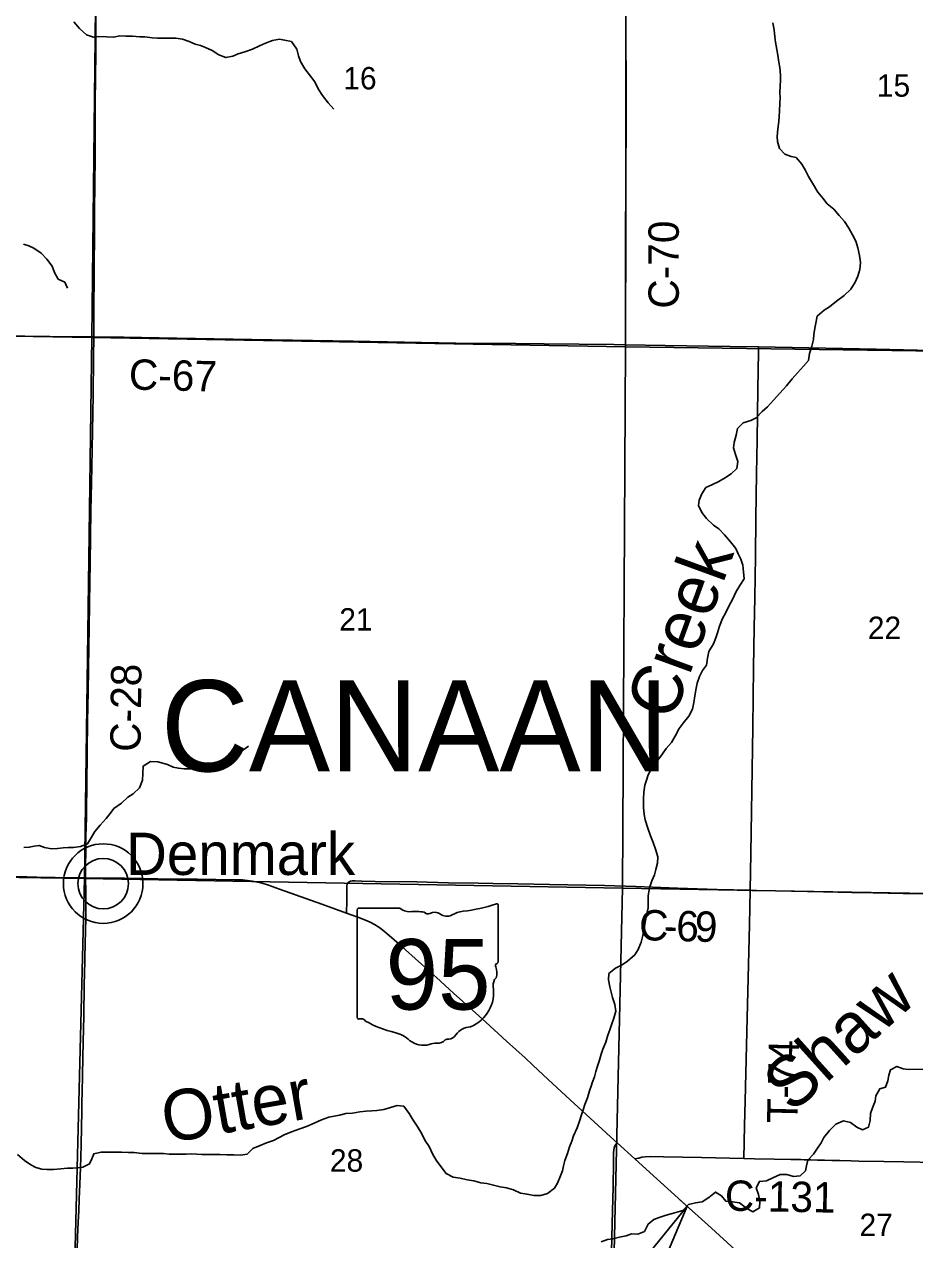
# Model space of a CAD drawing. Extents: x 0 to 34, y 0 to 22.
# Drawn here: x 4.92 to 6.585, y 17.017 to 19.29 of the extents above; entities that cross this region are included whole.
import ezdxf

# ---------------------------------------------------------------- set-up
doc = ezdxf.new("R2010")
doc.units = 0
for name, color, linetype in [('GM_X_City_Street', 7, 'Continuous'), ('GM_X_Corporation_Text', 7, 'Continuous'), ('GM_X_County_Road', 7, 'Continuous'), ('GM_X_County_Road_Text', 7, 'Continuous'), ('GM_X_Interchange_Ramps', 7, 'Continuous'), ('GM_X_Major_River_Text', 7, 'Continuous'), ('GM_X_Minor_Lake', 7, 'Continuous'), ('GM_X_Minor_River', 7, 'Continuous'), ('GM_X_Minor_River_Text', 7, 'Continuous'), ('GM_X_Section', 7, 'Continuous'), ('GM_X_State_Location', 7, 'Continuous'), ('GM_X_Township_Road_Text', 7, 'Continuous'), ('GM_X_Township_Text', 7, 'Continuous'), ('GM_X_Unincorporated_Location', 7, 'Continuous'), ('GM_X_Unincorporated_Text', 7, 'Continuous'), ('SH_Border', 7, 'Continuous'), ('SH_Cut_Line', 7, 'Continuous')]:
    doc.layers.add(name, color=color, linetype=linetype)

msp = doc.modelspace()

# ---------------------------------------------------------------- linework, layer by layer
at = {"layer": 'GM_X_City_Street'}
for points in [[(5.05, 18.7053), (5.0501, 18.7132), (5.0503, 18.7629), (5.0507, 18.8157), (5.051, 18.8437), (5.0514, 18.8903), (5.0516, 18.9431), (5.0519, 18.9897), (5.0523, 19.0425), (5.0526, 19.0829), (5.0527, 19.1326), (5.0532, 19.201), (5.0535, 19.2258), (5.0537, 19.2973), (5.0539, 19.3563), (5.054, 19.3874), (5.0546, 19.4278), (5.055, 19.4806), (5.0554, 19.5334), (5.0554, 19.5863), (5.0563, 19.6888), (5.056, 19.7161)], [(6.0443, 18.6905), (6.0443, 18.699), (6.0442, 18.727), (6.0449, 18.8855), (6.0452, 18.9819), (6.0454, 19.1342), (6.0454, 19.1994), (6.0452, 19.2461), (6.0451, 19.2771), (6.0458, 19.3486), (6.0463, 19.4294), (6.0459, 19.4698), (6.0462, 19.5071), (6.0463, 19.6066), (6.0465, 19.6781), (6.0463, 19.7017)], [(5.0346, 17.6937), (5.0346, 17.719), (5.035, 17.7408), (5.0354, 17.7718), (5.0361, 17.806), (5.0365, 17.8215), (5.0369, 17.865), (5.0376, 17.9303), (5.0385, 17.9862), (5.0394, 18.0421), (5.0407, 18.126), (5.0413, 18.1602), (5.0417, 18.2068), (5.0427, 18.2473), (5.0432, 18.2816), (5.0438, 18.331), (5.0445, 18.3807), (5.045, 18.4056), (5.0462, 18.4615), (5.0488, 18.5965), (5.0495, 18.6666), (5.05, 18.7053)], [(5.05, 18.7053), (5.1061, 18.7047), (5.2055, 18.7027), (5.3453, 18.7004), (5.5348, 18.6972), (5.7273, 18.6937), (5.8392, 18.6927), (5.892, 18.6923), (6.0225, 18.6908), (6.0443, 18.6905)], [(6.0443, 18.6905), (6.1188, 18.6894), (6.2399, 18.6875), (6.2929, 18.6864)], [(6.2929, 18.6864), (6.5133, 18.6821), (6.6158, 18.6801), (6.7887, 18.6761)], [(5.018, 16.9749), (5.0198, 17.0214), (5.021, 17.0493), (5.0218, 17.071), (5.0226, 17.0927), (5.0237, 17.1207), (5.0249, 17.1517), (5.0256, 17.1703), (5.0265, 17.1952), (5.0277, 17.2573), (5.0279, 17.2759), (5.0281, 17.2912), (5.0287, 17.3256), (5.0303, 17.3877), (5.0311, 17.4343), (5.0323, 17.4933), (5.0332, 17.5368), (5.0341, 17.5774), (5.0342, 17.5873), (5.0345, 17.5954), (5.0346, 17.6013), (5.0349, 17.6106), (5.0349, 17.6229), (5.0351, 17.6322), (5.0352, 17.6446), (5.0351, 17.657), (5.035, 17.6697), (5.0346, 17.6911), (5.0346, 17.6937)], [(5.5224, 17.6277), (5.5224, 17.629), (5.5229, 17.637), (5.5231, 17.6415), (5.5232, 17.6478), (5.523, 17.6664), (5.5231, 17.6757), (5.5234, 17.6787), (5.5241, 17.6815), (5.5254, 17.684), (5.5275, 17.6859), (5.53, 17.6871), (5.5329, 17.6877), (5.5359, 17.6879), (5.539, 17.6879), (5.5514, 17.6875), (5.5762, 17.6868), (5.6539, 17.6858), (5.7129, 17.6844), (5.7688, 17.6835), (5.7967, 17.6829), (5.8433, 17.6825), (5.9023, 17.6812), (6.0048, 17.6791), (6.0638, 17.6772), (6.1414, 17.6743), (6.2159, 17.6717), (6.2774, 17.6702)], [(6.2774, 17.6702), (6.2811, 17.67), (6.3246, 17.6691), (6.4146, 17.6672), (6.4674, 17.6663), (6.5078, 17.6653), (6.5637, 17.6644), (6.6196, 17.6635), (6.6627, 17.663)], [(6.0058, 16.4159), (6.0064, 16.4467), (6.0076, 16.5181), (6.0089, 16.5992), (6.01, 16.6488), (6.0107, 16.6889), (6.0123, 16.7546), (6.0136, 16.8039), (6.0142, 16.8445), (6.0156, 16.8942), (6.0159, 16.9159), (6.0165, 16.9381), (6.0175, 16.9654), (6.018, 16.9934), (6.0187, 17.0215), (6.0201, 17.0708), (6.0212, 17.1147), (6.0221, 17.161), (6.0222, 17.1798), (6.0231, 17.1887), (6.0242, 17.1923), (6.026, 17.1948), (6.0285, 17.1978)], [(6.0617, 17.1677), (6.069, 17.1695), (6.075, 17.1709), (6.0811, 17.1717), (6.0904, 17.1721), (6.1152, 17.1718), (6.1864, 17.1703), (6.2658, 17.1687)], [(6.2658, 17.1687), (6.2855, 17.1681), (6.3227, 17.1675), (6.3537, 17.1669), (6.3723, 17.1665), (6.3784, 17.1663), (6.3908, 17.166), (6.4033, 17.1657), (6.4163, 17.1654), (6.4301, 17.165), (6.4451, 17.1647), (6.4666, 17.1642), (6.481, 17.1639), (6.5276, 17.1629), (6.5648, 17.1625), (6.6859, 17.1597)]]:
    msp.add_lwpolyline(points, dxfattribs=at)
at = {"layer": 'GM_X_County_Road'}
for points in [[(4.7827, 17.6976), (4.8688, 17.696), (4.9247, 17.6952), (4.9436, 17.6949)], [(4.9436, 17.6949), (4.9775, 17.6943), (5.0334, 17.6937), (5.0346, 17.6937), (5.0955, 17.6929), (5.1019, 17.6929), (5.1077, 17.6928), (5.12, 17.6924), (5.1417, 17.6922), (5.1976, 17.6913), (5.2442, 17.6908), (5.3126, 17.69), (5.3281, 17.6895), (5.3375, 17.6888), (5.3468, 17.6875), (5.356, 17.6857), (5.3651, 17.6834), (5.377, 17.6797), (5.3975, 17.6725), (5.4765, 17.6441), (5.5224, 17.6277), (5.5438, 17.62), (5.5583, 17.6145), (5.5669, 17.6107), (5.5752, 17.6063), (5.5831, 17.6012), (5.5906, 17.5956), (5.6027, 17.5858), (5.6214, 17.5694), (5.6628, 17.5318), (5.6907, 17.5071), (5.723, 17.478), (5.7577, 17.4468), (5.783, 17.4238), (5.8221, 17.3883), (5.8565, 17.3568), (5.8711, 17.3431)], [(5.8711, 17.3431), (5.8995, 17.3164), (5.9406, 17.2785), (5.9932, 17.23), (6.0161, 17.2091), (6.0285, 17.1978), (6.0617, 17.1677), (6.0897, 17.1423), (6.1497, 17.0881), (6.2052, 17.0383), (6.2497, 16.9979)]]:
    msp.add_lwpolyline(points, dxfattribs=at)
at = {"layer": 'GM_X_Interchange_Ramps'}
for points in [[(4.0274, 18.7218), (4.0418, 18.7216), (4.1008, 18.7207), (4.1785, 18.7188), (4.3276, 18.7156), (4.486, 18.7127), (4.6942, 18.7096), (4.8744, 18.7071), (4.9676, 18.7057), (5.0471, 18.7054), (5.05, 18.7053)], [(6.2774, 17.6702), (6.2788, 17.739), (6.2822, 17.9749), (6.284, 18.0867), (6.2852, 18.1611), (6.2862, 18.217), (6.2872, 18.2946), (6.2884, 18.366), (6.2895, 18.4498), (6.2904, 18.5119), (6.292, 18.6081), (6.2928, 18.6764), (6.2929, 18.6864)], [(6.2658, 17.1687), (6.2669, 17.2301), (6.2679, 17.2766), (6.2717, 17.4318), (6.2761, 17.6056), (6.2774, 17.6702)]]:
    msp.add_lwpolyline(points, dxfattribs=at)
at = {"layer": 'GM_X_Section'}
for points in [[(5.0129, 19.2947), (5.0231, 19.2822), (5.0365, 19.2701), (5.0494, 19.266), (5.0596, 19.2668), (5.074, 19.2665), (5.0869, 19.2657), (5.0987, 19.2681), (5.1101, 19.2677), (5.1226, 19.2678), (5.1362, 19.2667), (5.1457, 19.2663), (5.1594, 19.2645), (5.1689, 19.2637), (5.2034, 19.2639), (5.2159, 19.2624), (5.2285, 19.2575), (5.2398, 19.2526), (5.2497, 19.2504), (5.2592, 19.2462), (5.2714, 19.2409), (5.2839, 19.2326), (5.2972, 19.2278), (5.3101, 19.2305), (5.3199, 19.2347), (5.3325, 19.2385), (5.3465, 19.2435), (5.3597, 19.2496), (5.3711, 19.2549), (5.384, 19.2599), (5.3972, 19.2618), (5.4067, 19.2604), (5.4196, 19.2578), (5.4295, 19.2434), (5.4326, 19.2309), (5.4368, 19.2203), (5.4445, 19.2066), (5.4551, 19.1926), (5.4635, 19.1824), (5.4693, 19.1695), (5.4776, 19.1567), (5.4883, 19.1431), (5.4986, 19.131)], [(6.2528, 18.4591), (6.2546, 18.472), (6.2504, 18.4853), (6.2466, 18.4978), (6.2477, 18.508), (6.2514, 18.5213), (6.2537, 18.5339), (6.2646, 18.5445), (6.2787, 18.5491), (6.2885, 18.5537), (6.2998, 18.5659), (6.31, 18.5746), (6.321, 18.5868), (6.3327, 18.5997), (6.3456, 18.6138), (6.3561, 18.6267), (6.3663, 18.6381), (6.3773, 18.6507), (6.3864, 18.661), (6.3886, 18.6743), (6.3927, 18.6879), (6.3961, 18.7001), (6.3964, 18.7099), (6.3983, 18.7217), (6.4002, 18.7312), (6.4031, 18.7441), (6.416, 18.7551), (6.4258, 18.7616), (6.4391, 18.7719), (6.4531, 18.7826), (6.4659, 18.7947), (6.4742, 18.8077), (6.4787, 18.8187), (6.4825, 18.8312), (6.484, 18.8445), (6.482, 18.8577), (6.4789, 18.8718), (6.4751, 18.8843), (6.469, 18.8964), (6.4621, 18.9089), (6.4541, 18.921), (6.4442, 18.932), (6.4339, 18.9441), (6.4217, 18.9543), (6.4134, 18.9645), (6.4038, 18.9758), (6.3939, 18.9928), (6.3867, 19.005), (6.3813, 19.0163), (6.3741, 19.0284), (6.3634, 19.0405), (6.3539, 19.0424), (6.3425, 19.0473), (6.3322, 19.0579), (6.3288, 19.0704), (6.328, 19.0799), (6.3291, 19.0943), (6.3309, 19.1079), (6.3317, 19.1174), (6.3324, 19.1273), (6.3327, 19.1424), (6.3334, 19.1523), (6.333, 19.1622), (6.3337, 19.1739), (6.3341, 19.1853), (6.334, 19.1948), (6.3332, 19.2092), (6.3313, 19.2191), (6.3294, 19.2323), (6.3274, 19.2429), (6.3251, 19.2566), (6.3239, 19.2664), (6.3224, 19.2797), (6.3197, 19.2926)], [(4.9184, 18.8787), (4.9282, 18.8757), (4.9377, 18.8712), (4.9514, 18.8618), (4.9621, 18.8504), (4.972, 18.8376), (4.9766, 18.8254), (4.9834, 18.8133), (4.9956, 18.8077), (5.001, 18.7963)], [(5.9811, 17.306), (5.9822, 17.3098), (5.9863, 17.3216), (5.989, 17.3311), (5.9923, 17.341), (5.9953, 17.3509), (5.9987, 17.3638), (6.0021, 17.3733), (6.0074, 17.3862), (6.0111, 17.3995), (6.0152, 17.4093), (6.0182, 17.4188), (6.0228, 17.4313), (6.0261, 17.4439), (6.0242, 17.4568), (6.0203, 17.4696), (6.0177, 17.4795), (6.015, 17.4897), (6.0123, 17.503), (6.0134, 17.5144), (6.0255, 17.5247), (6.0383, 17.5308), (6.0482, 17.5376), (6.0618, 17.5498), (6.0682, 17.5593), (6.0738, 17.573), (6.0768, 17.5855), (6.0794, 17.5995), (6.0817, 17.6136), (6.0839, 17.6235), (6.0869, 17.6375), (6.0865, 17.6504), (6.0868, 17.6599), (6.0894, 17.6747), (6.0935, 17.688), (6.0988, 17.6994), (6.1011, 17.7088), (6.1044, 17.721), (6.1048, 17.7328), (6.1005, 17.7471), (6.0959, 17.7596), (6.0913, 17.7718), (6.086, 17.7865), (6.0814, 17.8017), (6.0791, 17.8119), (6.0779, 17.8252), (6.0782, 17.8411), (6.0789, 17.8536), (6.0804, 17.8666), (6.0834, 17.8764), (6.0868, 17.8859), (6.0932, 17.8981), (6.103, 17.911), (6.1136, 17.9254), (6.1207, 17.9357), (6.1306, 17.9464), (6.1381, 17.9597), (6.1445, 17.9726), (6.1521, 17.9825), (6.1626, 17.9961), (6.1694, 18.0087), (6.172, 18.0216), (6.1743, 18.0337), (6.1765, 18.0482), (6.1783, 18.0576), (6.1829, 18.0702), (6.1885, 18.0816), (6.1961, 18.0915), (6.1975, 18.1044), (6.2001, 18.1169), (6.2088, 18.1309), (6.2133, 18.1423), (6.2163, 18.1518), (6.2201, 18.1644), (6.2257, 18.1788), (6.2314, 18.1887), (6.2374, 18.2016), (6.2453, 18.2153), (6.2513, 18.2289), (6.2581, 18.2403), (6.2664, 18.2529), (6.2652, 18.2658), (6.2637, 18.2783), (6.2602, 18.2896), (6.2553, 18.2995), (6.2507, 18.3097), (6.2408, 18.3222), (6.2293, 18.335), (6.2187, 18.346), (6.2092, 18.3532), (6.1958, 18.3653), (6.1871, 18.377), (6.1806, 18.3899), (6.1821, 18.4001), (6.187, 18.4119), (6.1949, 18.4237), (6.2059, 18.4283), (6.2191, 18.4348), (6.2293, 18.4412), (6.2422, 18.4489), (6.2528, 18.4591)], [(4.9189, 17.7504), (4.9292, 17.7508), (4.9386, 17.7528), (4.9481, 17.7539), (4.9576, 17.7502), (4.9709, 17.7479), (4.9819, 17.7483), (4.9925, 17.7499), (5.002, 17.7503), (5.0119, 17.75), (5.0251, 17.7523), (5.0384, 17.7569), (5.0459, 17.7694), (5.052, 17.7804), (5.0618, 17.7919), (5.0731, 17.8044), (5.0807, 17.8139), (5.0875, 17.8234), (5.1015, 17.8333), (5.1139, 17.8444), (5.1238, 17.8508), (5.1355, 17.8619), (5.1408, 17.8759), (5.1415, 17.8888), (5.1422, 17.9025), (5.1558, 17.9109), (5.1695, 17.9105), (5.1877, 17.9053), (5.1983, 17.9008), (5.2082, 17.8985), (5.2188, 17.8971), (5.2317, 17.8975), (5.2469, 17.9002), (5.2598, 17.9021), (5.27, 17.9022), (5.2825, 17.9033), (5.2928, 17.9064), (5.3026, 17.9121), (5.3147, 17.9213), (5.3264, 17.9304), (5.3393, 17.9399)], [(6.6012, 17.3354), (6.5735, 17.3353), (6.5636, 17.336), (6.5519, 17.3409), (6.5397, 17.3345), (6.5367, 17.3242), (6.5349, 17.314), (6.5307, 17.3022), (6.5198, 17.2987), (6.5126, 17.2858), (6.5115, 17.276), (6.5062, 17.2634), (6.5025, 17.2528), (6.5018, 17.2399), (6.4988, 17.227), (6.4874, 17.2224), (6.4771, 17.2273), (6.465, 17.236), (6.4521, 17.239), (6.4377, 17.2329), (6.426, 17.2211), (6.4154, 17.2081), (6.4101, 17.1979), (6.4033, 17.188), (6.3962, 17.1766), (6.3852, 17.1652), (6.3826, 17.1549), (6.3807, 17.1454), (6.3709, 17.1359), (6.3584, 17.1347), (6.3462, 17.1389), (6.3337, 17.1388), (6.3201, 17.1327), (6.3079, 17.1266), (6.2947, 17.1258), (6.289, 17.114), (6.2929, 17.1015), (6.2959, 17.0879), (6.2952, 17.0761), (6.2827, 17.0689), (6.2706, 17.0757), (6.2573, 17.0855), (6.2447, 17.0873), (6.2318, 17.0888), (6.2238, 17.099), (6.2124, 17.1058), (6.2003, 17.0955), (6.1878, 17.0875), (6.175, 17.0856), (6.1624, 17.0825), (6.1519, 17.0715), (6.1344, 17.0665), (6.1204, 17.0626), (6.1075, 17.0581), (6.0973, 17.0546), (6.0867, 17.0458), (6.0799, 17.0322), (6.0674, 17.0272), (6.0557, 17.0275), (6.0458, 17.0241), (6.0333, 17.0214), (6.0204, 17.0183), (6.0109, 17.0168), (5.9988, 17.0126)], [(5.6689, 17.203), (5.6769, 17.1909), (5.6834, 17.1776), (5.6903, 17.1655), (5.699, 17.1538), (5.7089, 17.1405), (5.7219, 17.1334), (5.7352, 17.1315), (5.7481, 17.1289), (5.7606, 17.1267), (5.7739, 17.1233), (5.7849, 17.1218), (5.7951, 17.1192), (5.8099, 17.1155), (5.8221, 17.114), (5.835, 17.1099), (5.8483, 17.1038), (5.8604, 17.1016), (5.873, 17.0994), (5.8859, 17.0994), (5.8984, 17.1032), (5.9116, 17.1132), (5.9173, 17.1227), (5.9229, 17.1359), (5.9263, 17.1454), (5.9285, 17.1549), (5.9311, 17.1648), (5.9356, 17.1777), (5.9398, 17.1906), (5.9439, 17.2012), (5.9473, 17.2107), (5.9541, 17.2259), (5.9586, 17.2381), (5.9619, 17.2502), (5.9649, 17.2597), (5.9683, 17.2696), (5.9732, 17.2821), (5.9773, 17.2954), (5.9811, 17.306)], [(4.9073, 17.1762), (4.9206, 17.1648), (4.9324, 17.1569), (4.9419, 17.152), (4.9529, 17.1486), (4.9624, 17.1479), (4.9749, 17.1479), (4.9886, 17.1491), (5.0007, 17.1503), (5.0106, 17.1507), (5.02, 17.1511), (5.0295, 17.1523), (5.042, 17.1584), (5.0462, 17.1679), (5.0499, 17.1774), (5.0636, 17.1805), (5.1019, 17.1806), (5.1148, 17.1795), (5.1258, 17.1796), (5.1406, 17.1777), (5.1535, 17.1777), (5.1668, 17.1782), (5.1804, 17.1782), (5.191, 17.1767), (5.2013, 17.1764), (5.2134, 17.1764), (5.2229, 17.1768), (5.2324, 17.1776), (5.2426, 17.1769), (5.2521, 17.1762), (5.2646, 17.1758), (5.2859, 17.1759), (5.2988, 17.1756), (5.312, 17.1756), (5.3242, 17.1749), (5.3367, 17.1768), (5.3477, 17.1875), (5.3613, 17.1929), (5.3727, 17.1978), (5.3863, 17.2024), (5.3965, 17.2081), (5.4071, 17.2135), (5.4219, 17.2189), (5.4355, 17.2242), (5.448, 17.2284), (5.462, 17.2349), (5.4757, 17.241), (5.4893, 17.2456), (5.4996, 17.2476), (5.5094, 17.2495), (5.5212, 17.2526), (5.5341, 17.2534), (5.5473, 17.2557), (5.5595, 17.2572), (5.5701, 17.2577), (5.5796, 17.2584), (5.5924, 17.26), (5.605, 17.2642), (5.6175, 17.268), (5.6296, 17.2662), (5.6395, 17.253), (5.6471, 17.2401), (5.6559, 17.2272), (5.6632, 17.2147), (5.6689, 17.203)]]:
    msp.add_lwpolyline(points, dxfattribs=at)
at = {"layer": 'GM_X_State_Location'}
for p, q in [((5.8062, 17.5368), (5.8062, 17.6415)), ((5.5425, 17.6331), (5.5425, 17.4329)), ((5.6224, 17.6365), (5.5451, 17.6365)), ((5.8062, 17.5368), (5.8062, 17.5368))]:
    msp.add_line(p, q, dxfattribs=at)
for centre, radius, start, end in [((5.7123, 17.9093), 0.2796, 275.8445, 288.9065), ((5.8033, 17.6419), 0.00294, 351.8621, 97.738), ((5.5456, 17.6335), 0.00305, 98.1301, 188.1301), ((5.6407, 17.6597), 0.0296, 231.6195, 271.1119), ((5.6506, 17.5242), 0.1064, 80.4867, 94.9883), ((5.6747, 17.6345), 0.00855, 219.7921, 297.1024), ((5.6873, 17.6114), 0.0178, 54.4667, 119.1411), ((5.7102, 17.6431), 0.0214, 233.8562, 294.8282), ((5.748, 17.5754), 0.0563, 97.3462, 120.7689), ((5.8055, 17.5291), 0.00454, 107.944, 210.337), ((5.7766, 17.5159), 0.0273, 340.033, 23.6496), ((5.8031, 17.5364), 0.00314, 289.6038, 7.7341), ((5.8167, 17.493), 0.0198, 136.8065, 186.9296), ((5.7279, 17.4796), 0.0699, 292.3089, 8.9858), ((5.5456, 17.4325), 0.00308, 171.9584, 258.3066), ((5.5461, 17.453), 0.0235, 267.339, 280.6039), ((5.5509, 17.4214), 0.00848, 29.7484, 93.2717), ((5.6579, 17.6012), 0.2019, 240.4129, 257.1985), ((5.7574, 17.3768), 0.0383, 94.4031, 142.5768), ((5.5977, 17.343), 0.0632, 47.1842, 75.836), ((5.6921, 17.4054), 0.0214, 268.777, 315.5493), ((5.7115, 17.386), 0.00601, 65.7517, 132.6484), ((5.7089, 17.4135), 0.0226, 282.8732, 323.2771), ((5.6661, 17.4204), 0.0401, 230.7004, 286.2918), ((5.6892, 17.3512), 0.0329, 85.6951, 111.2099)]:
    msp.add_arc(centre, radius, start, end, dxfattribs=at)
at = {"layer": 'GM_X_Township_Text'}
for radius in [0.0744, 0.0472]:
    msp.add_circle((5.0676, 17.6827), radius, dxfattribs=at)
at = {"layer": 'GM_X_Unincorporated_Location'}
for points in [[(4.0319, 19.7295), (5.0575, 19.7147), (5.0466, 18.7043), (4.0237, 18.7217)], [(5.0575, 19.7147), (6.0459, 19.7005), (6.0441, 18.6866), (5.0466, 18.7043)], [(6.0459, 19.7005), (7.0617, 19.6888), (7.0397, 18.6727), (6.0441, 18.6866)], [(4.0237, 18.7217), (5.0466, 18.7043), (5.0326, 17.6924), (4.0116, 17.7079)], [(5.0466, 18.7043), (6.0441, 18.6866), (6.0388, 17.6742), (5.0326, 17.6924)], [(6.0441, 18.6866), (7.0397, 18.6727), (7.0045, 17.6571), (6.0388, 17.6742)], [(5.0326, 17.6924), (5.0069, 16.682), (3.9996, 16.6997), (4.0116, 17.7079)], [(6.0388, 17.6742), (6.0154, 16.6684), (5.0069, 16.682), (5.0326, 17.6924)], [(7.0045, 17.6571), (7.0019, 16.6421), (6.0154, 16.6684), (6.0388, 17.6742)]]:
    msp.add_lwpolyline(points, close=True, dxfattribs=at)
at = {"layer": 'GM_X_Unincorporated_Text'}
msp.add_line((5.0676, 17.6827), (5.0676, 17.6827), dxfattribs=at)
at = {"layer": 'SH_Border'}
msp.add_lwpolyline([(6.1594, 17.0794), (5.7456, 16.5696), (5.7384, 16.0796)], close=True, dxfattribs=at)
at = {"layer": 'SH_Cut_Line'}
msp.add_line((6.1453, 17.0921), (6.1754, 17.065), dxfattribs=at)

# ---------------------------------------------------------------- texts
at = {"layer": 'GM_X_Corporation_Text'}
msp.add_text('CANAAN', height=0.17045, rotation=0, dxfattribs=at).set_placement((5.1754, 17.8927))
at = {"layer": 'GM_X_County_Road_Text'}
msp.add_text('T-74', height=0.05682, rotation=88.5837, dxfattribs=at).set_placement((6.3656, 17.2336))
at = {"layer": 'GM_X_Major_River_Text'}
for s, p in [('16', (5.5166, 19.1682)), ('15', (6.5145, 19.1545)), ('21', (5.5091, 18.156)), ('22', (6.4975, 18.1402)), ('28', (5.4916, 17.144)), ('27', (6.482, 17.0236))]:
    msp.add_text(s, height=0.04186, rotation=0, dxfattribs=at).set_placement(p)
at = {"layer": 'GM_X_Minor_Lake'}
msp.add_text('Denmark', height=0.07898, rotation=0, dxfattribs=at).set_placement((5.1104, 17.6989))
at = {"layer": 'GM_X_Minor_River'}
for s, height, rotation, p in [('Creek', 0.09472, 69.9727, (6.1324, 17.9843)), ('Shaw', 0.09471, 41.9741, (6.3562, 17.2516)), ('Otter', 0.09471, 9.9753, (5.1857, 17.1966))]:
    msp.add_text(s, height=height, rotation=rotation, dxfattribs=at).set_placement(p)
at = {"layer": 'GM_X_Minor_River_Text'}
for s, height, rotation, p in [('C-70', 0.05682, 90, (6.1441, 18.7581)), ('C-67', 0.05682, 358.6285, (5.1151, 18.6069)), ('C-28', 0.05682, 89.3202, (5.1374, 17.929)), ('C', 0.0568, 358.4935, (6.0692, 17.5771)), ('6', 0.0568, 358.4981, (6.1387, 17.5753)), ('9', 0.0568, 358.5178, (6.1734, 17.5744)), ('-', 0.0568, 358.4937, (6.1155, 17.5759)), ('C-131', 0.05682, 358.9025, (6.2299, 17.0711))]:
    msp.add_text(s, height=height, rotation=rotation, dxfattribs=at).set_placement(p)
at = {"layer": 'GM_X_State_Location'}
msp.add_text('95', height=0.13184, dxfattribs=at).set_placement((5.5958, 17.4471))
at = {"layer": 'GM_X_Township_Road_Text'}
msp.add_text('95', height=0.000189, rotation=0, dxfattribs=at).set_placement((5.6237, 17.5059))
for s in ['s', 'r']:
    msp.add_text(s, height=0.000189, dxfattribs=at).set_placement((5.6714, 17.5197))

doc.saveas('drawing.dxf')
